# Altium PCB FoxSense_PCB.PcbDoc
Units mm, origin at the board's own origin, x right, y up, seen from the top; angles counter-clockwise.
Board outline 79.5 x 55 mm, 2 copper layers (Top Layer, Bottom Layer), stack 1.569 mm thick; 35 components, 44 nets, 152 pads, 33 vias.
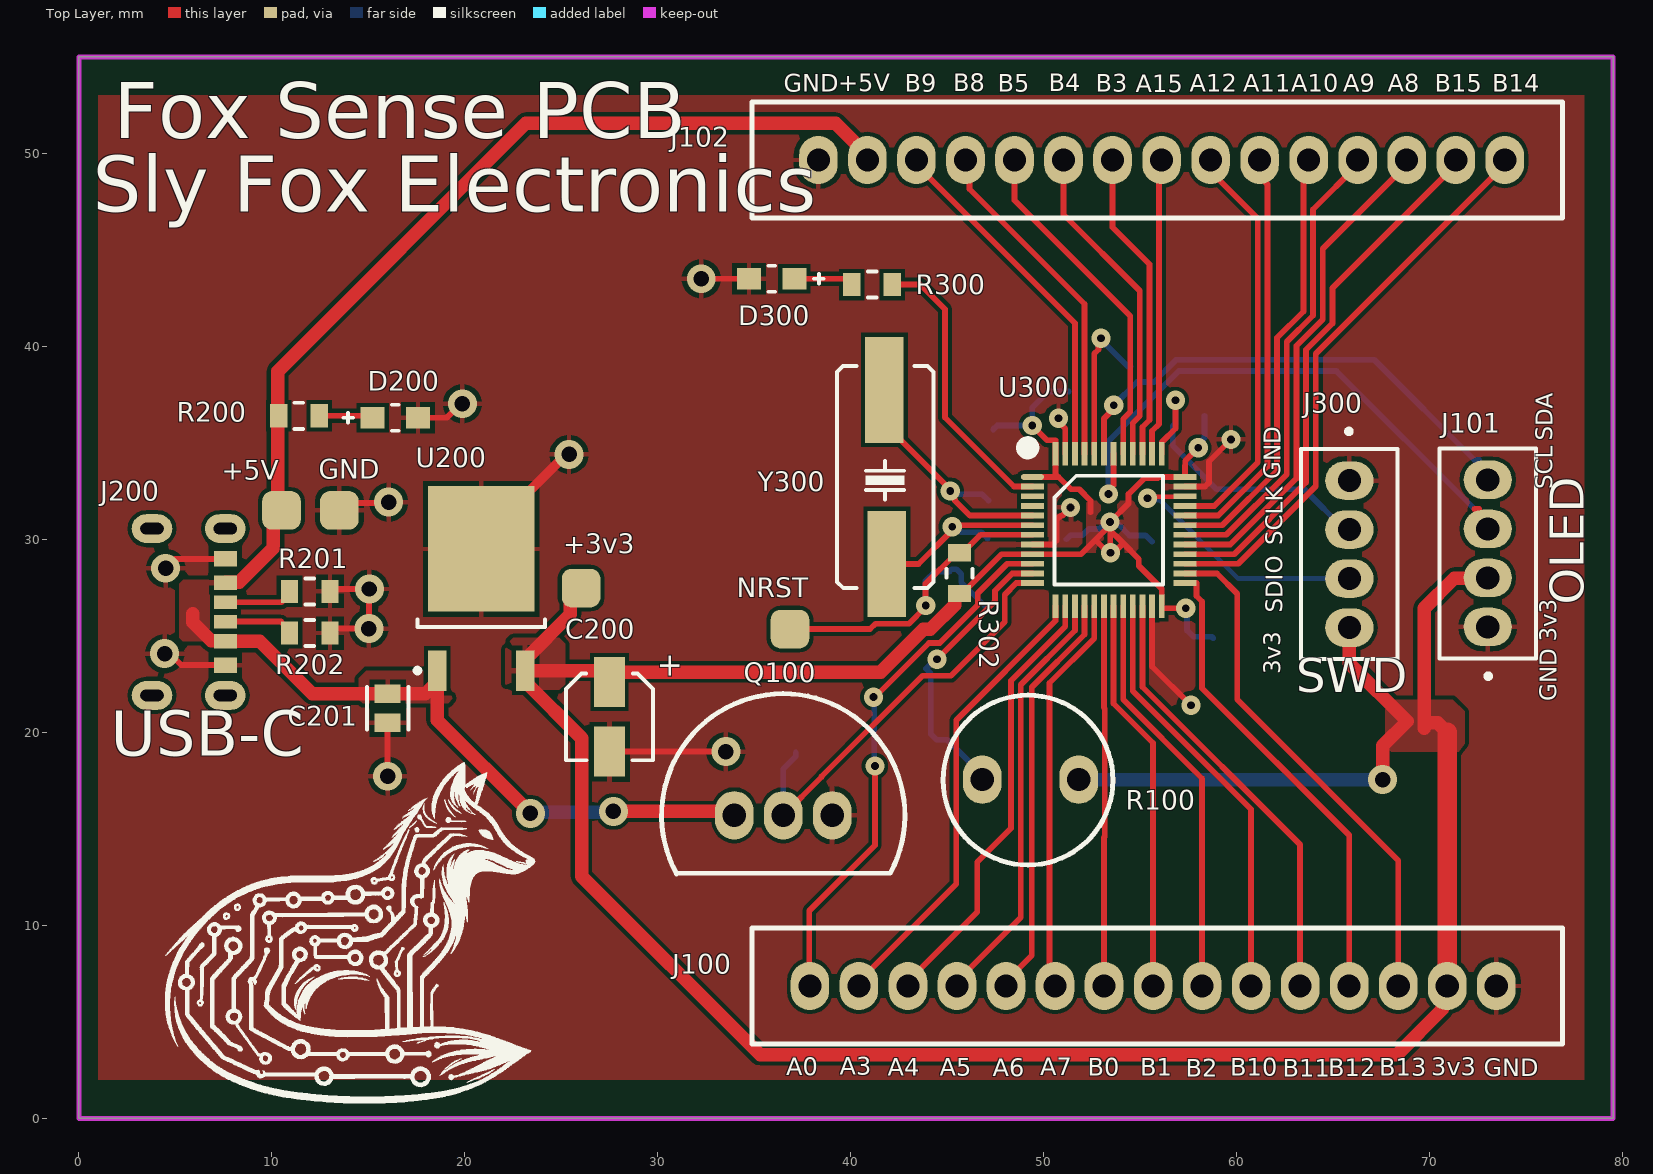
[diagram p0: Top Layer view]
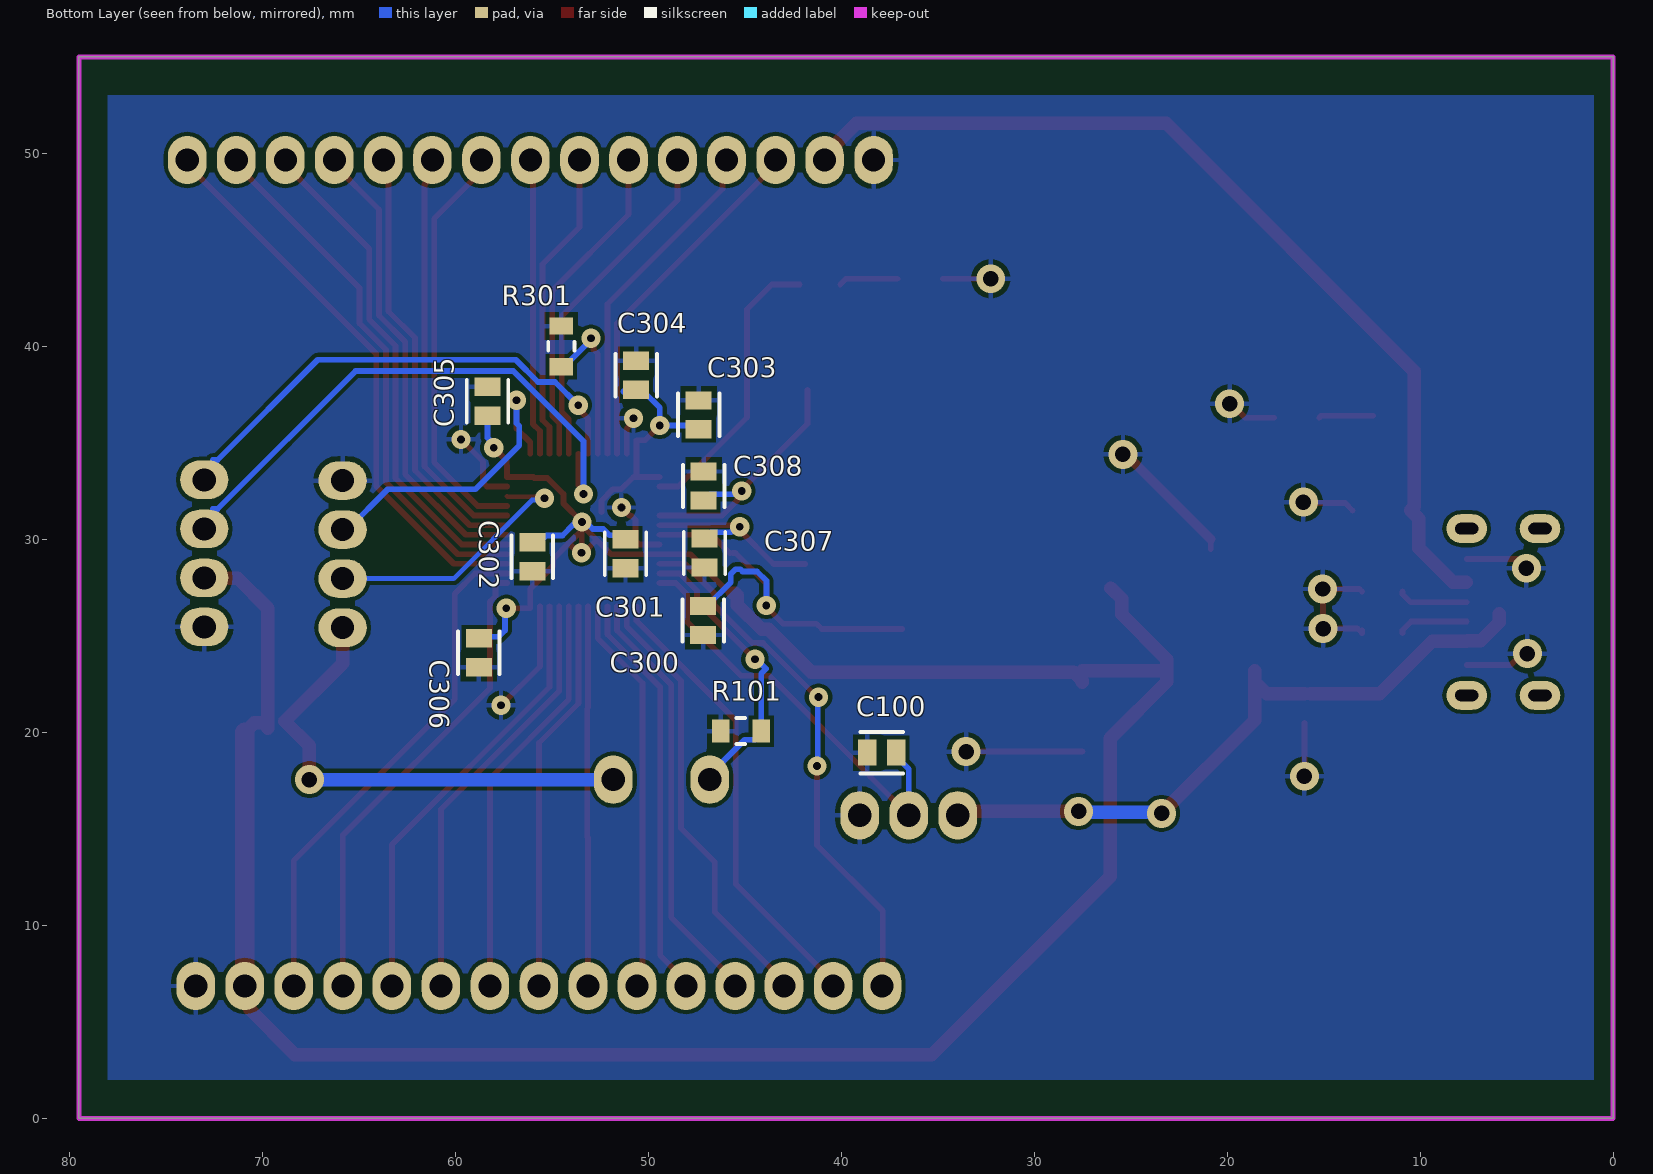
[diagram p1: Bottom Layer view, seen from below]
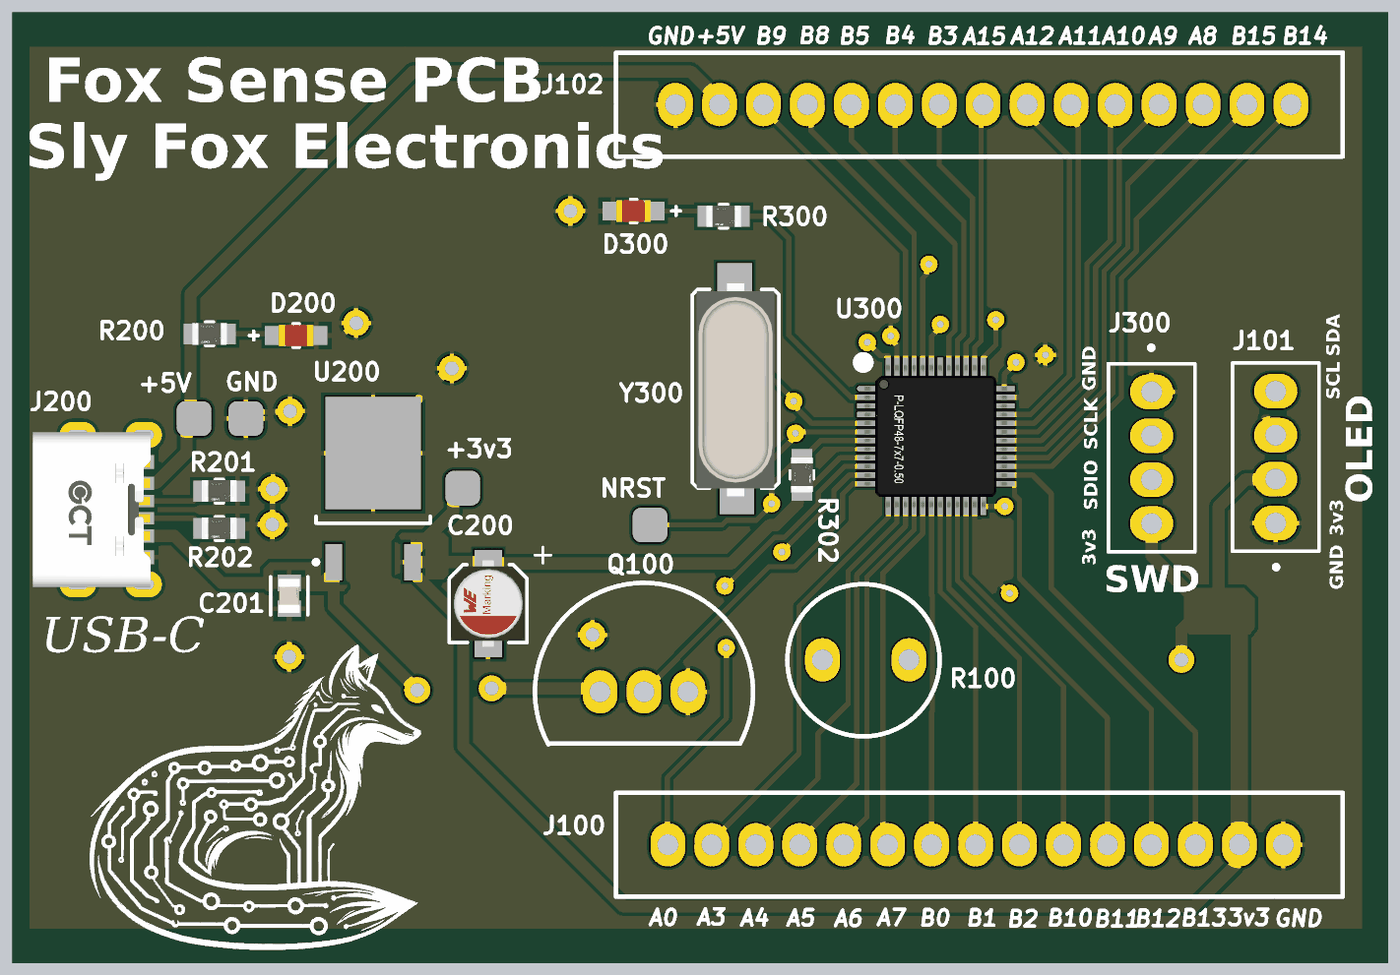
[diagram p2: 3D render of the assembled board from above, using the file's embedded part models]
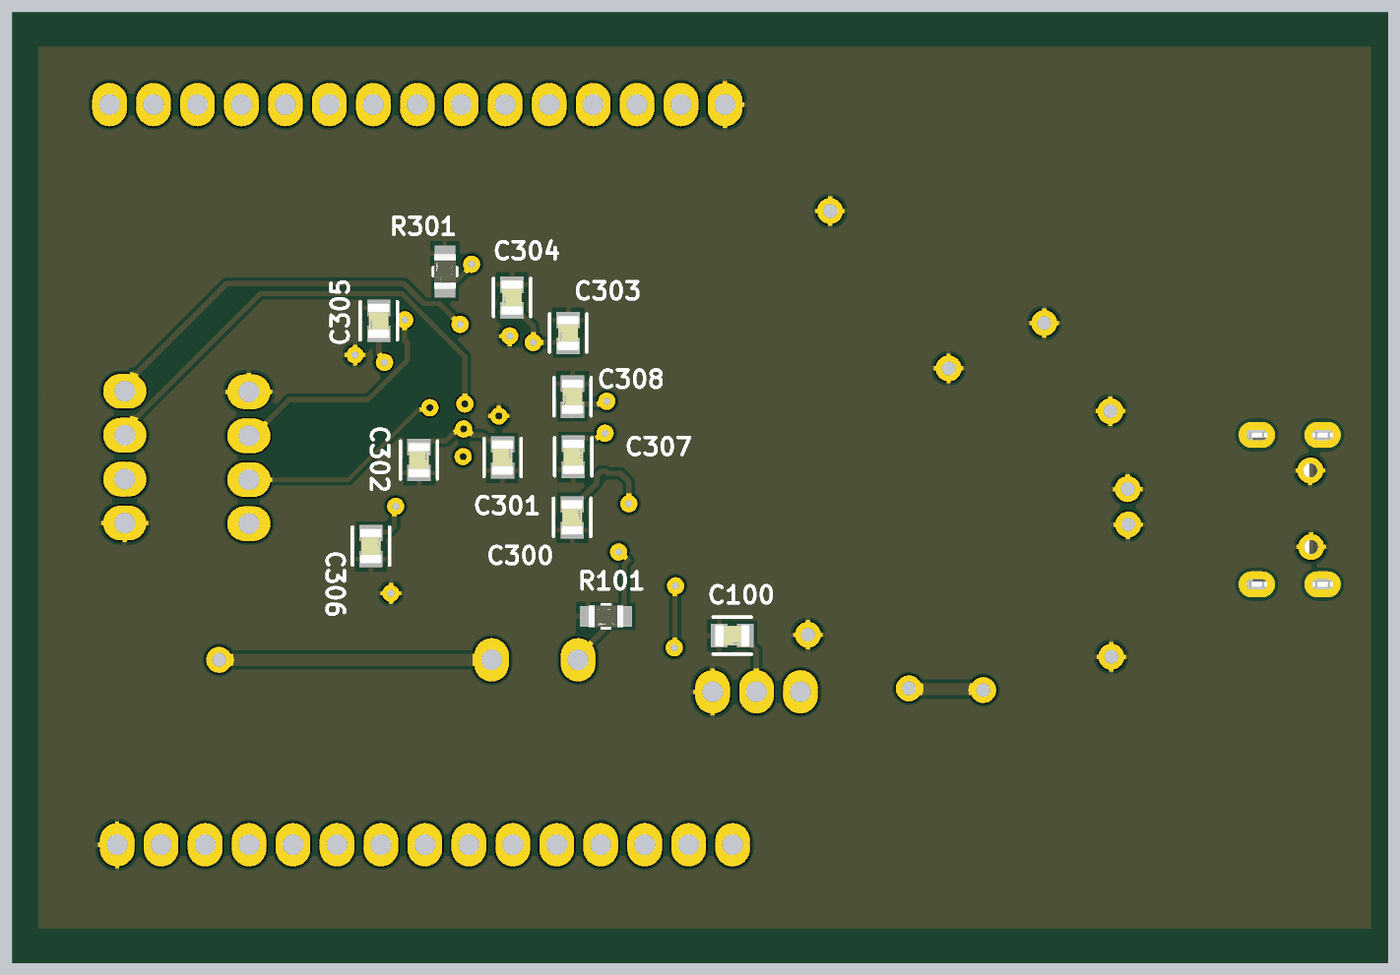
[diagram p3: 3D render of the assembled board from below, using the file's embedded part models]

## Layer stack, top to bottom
Top Solder: solder mask 0.0254, SM-001, Dk 4
Top Layer: signal copper 0.035
Dielectric 1: core 1.4986, Core-043, Dk 4.3
Bottom Layer: signal copper 0.035
Bottom Solder: solder mask 0.0254, SM-001, Dk 4

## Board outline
0,0 0,55 79.5,55 79.5,0

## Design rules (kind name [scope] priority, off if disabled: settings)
Clearance [All] p1: gap=0.2 ignorepadtopadclearanceinfootprint=TRUE
HoleSize [All] p1: absolutevalues=TRUE maxlimit=2.54 minlimit=0.04 maxpercent=80.000 minpercent=20.000
MinimumAnnularRing [All] p1: minimumring=0.3
MinimumSolderMaskSliver [All] p1: minsoldermaskwidth=0.2
PolygonConnect [All] p1: connectstyle=Relief reliefconductorwidth=0.254 reliefentries=4 polygonreliefangle="90 Angle" airgapwidth=0.254
RoutingVias [All] p1: holewidth=0.8 width=1.5 viastyle="Through Hole" minholewidth=0.4 minwidth=0.8 maxholewidth=0.8 maxwidth=1.5
SilkToSolderMaskClearance [IsPad] p1: minsilkscreentomaskgap=0.2 clearancetoexposedcopper=TRUE
SolderMaskExpansion [All] p1: expansion=0.102 istentingtop=FALSE
SupplyNets "Schematic Supply Nets" [InNet('GND')] p1: voltage=0.000
SupplyNets "Schematic Supply Nets_2" [InNet('+3v3')] p2: voltage=0.000
SupplyNets "Schematic Supply Nets_1" [InNet('+5V')] p3: voltage=0.000
Width [All] p1: maxlimit=2 minlimit=0.25 preferedwidth=0.7
27 further rules are at their usual default settings.

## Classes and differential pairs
component class FoxSense_Schematic: C100 J100 J101 J102 Q100 R100 R101
component class U_FoxSense_Power: +3v3 +5V C200 C201 D200 GND J200 R200 R201 R202 U200
component class U_FoxSense_Microcontroller: C300 C301 C302 C303 C304 C305 C306 C307 C308 D300 J300 NRST R300 R301 R302 U300 Y300

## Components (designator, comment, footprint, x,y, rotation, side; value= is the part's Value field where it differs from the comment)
+3v3 "Test_Point_SMD" TEST_Point_SMD 26,27.5 r90 top (schematic designator T201)
+5V "Test_Point_SMD" TEST_Point_SMD 10.475,31.525 r90 top (schematic designator T202)
C100 "100nF" Capacitor_SMD_0805 37.9,18.8 r270 bottom
C200 "2.2uF" Capacitor_SMD_Electrolyte_2.2uF 27.279,21.319 r90 top
C201 "100nF" Capacitor_SMD_0805 16.15,21.25 r0 top
C300 "100nF" Capacitor_SMD_0805 47.001,25.791 r180 bottom
C301 "100nF" Capacitor_SMD_0805 51.025,29.25 r180 bottom
C302 "1uF" Capacitor_SMD_0805 55.85,29.1 r180 bottom
C303 "10uF" Capacitor_SMD_0805 47.532,36.447 r0 bottom
C304 "100nF" Capacitor_SMD_0805 50.775,38.5 r0 bottom
C305 "100nF" Capacitor_SMD_0805 58.475,37.15 r0 bottom
C306 "100nF" Capacitor_SMD_0805 58.625,24.125 r180 bottom
C307 "20pF" Capacitor_SMD_0805 46.933,29.291 r180 bottom
C308 "20pF" Capacitor_SMD_0805 47.278,32.764 r0 bottom
D200 "LED_SMD_0805" LED_SMD_0805 16.1,36.2 r0 top
D300 "RED LED" LED_SMD_0805 36.2,43.6 r180 top
GND "Test_Point_SMD" TEST_Point_SMD 13.475,31.525 r90 top (schematic designator T200)
J100 "Header pin 15" Header15 37.88,6.881 r0 top
J101 "OLED" Header4 73,25.46 r90 top
J102 "Header pin 15" Header15 73.88,49.63 r180 top
J200 "USB_C_6_pin" USB_C_6_pin 4.792,26.16 r0 top
J300 "Pin_Header_4" Header4 65.831,33.045 r270 top
NRST "Test_Point_SMD" TEST_Point_SMD 36.825,25.375 r90 top (schematic designator T300)
Q100 "LM35 DZ" LM35 36.5,15.7 r180 top
R100 "LDR" LDR 49.183,17.524 r180 top
R101 "10K ohm" Resistor_SMD_0805 44.992,20.064 r0 bottom
R200 "330 ohm" Resistor_SMD_0805 11.6,36.4 r180 top
R201 "5.1k ohm" Resistor_SMD_0805 12.166,27.303 r180 top
R202 "5.1k ohm" Resistor_SMD_0805 12.166,25.144 r180 top
R300 "330 ohm" Resistor_SMD_0805 41.3,43.2 r180 top
R301 "10K ohm" Resistor_SMD_0805 54.5,39.8 r90 bottom
R302 "10K ohm" Resistor_SMD_0805 45.627,28.446 r270 top
U200 "LF33_DPAK" LF33 20.5,27.5 r0 top
U300 "STM32f103c8t6_LQFP48" STM32f103c8t6_LQFP48 49.411,33.232 r0 top
Y300 "XTAL 8MHz" Crystal_Resonator_SMD_XTAL 41.69,33.145 r0 top

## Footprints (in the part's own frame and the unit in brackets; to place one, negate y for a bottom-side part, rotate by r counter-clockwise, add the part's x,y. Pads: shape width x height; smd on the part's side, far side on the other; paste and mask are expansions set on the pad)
Capacitor_SMD_0805 [mm] "capacitor smd 0805"
  rect 1.35x0.95 smd paste+0 mask+0: 1(-0.15,0.75) 2(-0.15,-0.75)
  silkscreen extent -1.22,-1.1 0.92,1.1, body extent -0.77,-1 0.48,1, height 0.88
Capacitor_SMD_Electrolyte_2.2uF [mm] "Capacitor SMD Electrolyte 2.2uF"
  rect 2.6x1.6 smd: 1(1.281,-0.221) 2(-2.319,-0.221)
  silkscreen extent -2.77,-2.47 1.73,2.03, body extent -3.02,-2.37 1.98,1.93, height 5.5
Crystal_Resonator_SMD_XTAL [mm] "crystal ceramic resonator xtal"
  rect 2x5.5 smd: 1(0.176,-4.419) 2(0.049,4.598)
  silkscreen extent -2.4,-5.67 2.6,5.83, body extent -2.15,-6.13 2.35,6.17, height 5.18
Header4 [mm]
  oval 2x2.5 hole 1.2: 1(0,0) 2(2.54,0) 3(5.08,0) 4(7.62,0)
  silkscreen extent -2.67,-2.5 9.26,2.5
Header15 [mm] "Header pin 15"
  oval 2x2.5 hole 1.2: 1(0,-0.025) 2(2.54,-0.025) 3(5.08,-0.025) 4(7.62,-0.025) 5(10.16,-0.025) 6(12.7,-0.025) 7(15.24,-0.025) 8(17.78,-0.025) 9(20.32,-0.025) 10(22.86,-0.025) 11(25.4,-0.025) 12(27.94,-0.025) 13(30.48,-0.025) 14(33.02,-0.025) 15(35.56,-0.025)
  silkscreen extent -3,-3.03 39,2.97
LDR [mm] "LDR DIP"
  oval 2x2.5 hole 1.2: 1(-2.625,-0.025) 2(2.375,-0.025)
  silkscreen extent -4.4,-4.4 4.4,4.4
LED_SMD_0805 [mm] "LED SMD 0805"
  rect 1.25x1.1 smd paste+0 mask+0: 1(-0.875,0.1) 2(1.475,0.1)
  silkscreen extent -2.4,-0.58 0.48,0.77, body extent -1.6,-0.67 2.2,0.87, height 0.25
LF33 [mm] "LF33 DPAK 3.3 voltage regulator"
  rect 0.95x2.1 smd: 1(-1.93,-4.3) 3(2.63,-4.3)
  rect 5.5x6.5 smd: 4(0.35,2)
  silkscreen extent -3.08,-4.42 3.65,-1.65, body extent -2.95,-2.05 3.65,4.15, height 2.4
LM35 [mm] "LM35 DZ Dip"
  oval 2x2.5 hole 1.2: 1(2.54,0) 2(0,0) 3(-2.54,0)
  silkscreen extent -6.3,-6.3 6.3,3.04
Resistor_SMD_0805 [mm] "resistor smd 0805"
  rect 0.9x1.2 smd paste+0 mask+0: 1(-0.85,0) 2(1.25,0)
  silkscreen extent -0.03,-0.67 0.43,0.67, body extent -0.8,-0.63 1.2,0.63, height 0.6
STM32f103c8t6_LQFP48 [mm]
  oval 1.2x0.3 smd: 1(0,0)
  rect 1.2x0.3 smd: 2(0,-0.5) 3(0,-1) 4(0,-1.5) 5(0,-2) 6(0,-2.5) 7(0,-3) 8(0,-3.5) 9(0,-4) 10(0,-4.5) 11(0,-5) 12(0,-5.5) 25(7.9,-5.5) 26(7.9,-5) 27(7.9,-4.5) 28(7.9,-4) 29(7.9,-3.5) 30(7.9,-3) 31(7.9,-2.5) 32(7.9,-2) 33(7.9,-1.5) 34(7.9,-1) 35(7.9,-0.5) 36(7.9,0)
  rect 0.3x1.2 smd: 13(1.2,-6.7) 14(1.7,-6.7) 15(2.2,-6.7) 16(2.7,-6.7) 17(3.2,-6.7) 18(3.7,-6.7) 19(4.2,-6.7) 20(4.7,-6.7) 21(5.2,-6.7) 22(5.7,-6.7) 23(6.2,-6.7) 24(6.7,-6.7) 37(6.7,1.2) 38(6.2,1.2) 39(5.7,1.2) 40(5.2,1.2) 41(4.7,1.2) 42(4.2,1.2) 43(3.7,1.2) 44(3.2,1.2) 45(2.7,1.2) 46(2.2,1.2) 47(1.7,1.2) 48(1.2,1.2)
  silkscreen extent -0.54,-5.56 6.76,1.81, body extent -0.55,-7.25 8.45,1.75, height 1.4
TEST_Point_SMD [mm] "TEST_Point_SMD"
  rrect50% 2x2 smd: 1(-0.025,-0.025)
USB_C_6_pin [mm] "USB C connector 6 pin"
  rrect100% 2.1x1.5 hole 1.2 slot 0.6 at 90 deg paste-2539.97 mask+0: 2(2.8,-4.245) 3(-1,4.395) 3(2.8,4.395) 4(-1,-4.245)
  rect 1.2x0.7 smd paste+0 mask+0: A5(2.8,0.575) B5(2.8,-0.425)
  rect 1.2x0.76 smd paste+0 mask+0: A9(2.8,-1.445) B9(2.8,1.595)
  rect 1.2x0.8 smd paste+0 mask+0: A12(2.8,-2.675) B12(2.8,2.825)
  body extent -3.77,-4.89 3.75,5.05, height 0.25

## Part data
+3v3 +5V GND NRST: "Test Point SMD"
C100 C300 C301 C304 C305 C306: library part Capacitor_SMD_0805, "capacitor smd 0805 100nF"
C200: library part Capacitor_SMD_Electrolyte_2.2uF, "Capacitor SMD Electrolyte 2.2uF"
C201 C302: library part Capacitor_SMD_0805, "capacitor smd 0805"
C303: library part Capacitor_SMD_0805, "capacitor smd 0805 10uF"
C307 C308: library part Capacitor_SMD_0805, "capacitor smd 0805 20pF"
D200: "LED SMD 0805"
D300: library part LED_SMD_0805, "LED SMD 0805"
J100 J102: library part Header15
J101: library part Header4, "OLED 0..96 inch"
J200: library part USB_C, "USB C connector 6 pin"
J300: library part Header4, "Pin Header 4"
Q100: library part LM35
R100: "LDR DIP"
R101: library part Resistor_SMD_0805, "Resistor SMD 0805 10 k ohm"
R200 R201 R202: library part Resistor_SMD_0805, "Resistor SMD 0805"
R300: library part Resistor_SMD_0805, "Resistor SMD 0805 330 ohm"
R301 R302: library part Resistor_SMD_0805, "Resistor SMD 0805 10k ohm"
U200: library part LF33, "LF33 DPAK 3.3 voltage regulator"
U300: library part STM32f103c8t6, "STM32f103c8t6 LQFP48"
Y300: library part "Crystal Resonator SMD", "crystal resonator SMD 8MHz"

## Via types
v1: diameter 1, hole 0.4, Top Layer to Bottom Layer, 20 vias
v2: diameter 1.5, hole 0.8, Top Layer to Bottom Layer, 13 vias

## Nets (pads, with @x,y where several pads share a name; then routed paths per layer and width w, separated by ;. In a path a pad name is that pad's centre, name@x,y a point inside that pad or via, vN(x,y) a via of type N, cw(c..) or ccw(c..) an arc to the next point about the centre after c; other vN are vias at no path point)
+3v3: +3v3.1 C200.1 C301.1 C302.1 C303.1 C304.1 C305.1 C306.1 J100.14 J101.2 J300.4 R100.1 R302.2 U200.3 U300.1 U300.9 U300.24 U300.36 U300.48 | length 191.7
  Top Layer w0.3: R302.2 45.777,27.196 47.813,29.232 U300.9 51.932,29.232 52.616,29.916 ; v1(49.4,35.9) 50.167,35.133 50.611,35.133 U300.48 50.611,33.387 50.766,33.232 ; U300.1 50.766,33.232 ; 52.425,31.4 52.425,32.002 51.835,32.592 51.406,32.592 50.766,33.232 ; v1(57.35,26.425) 56.111,26.425 56.111,27.439 54.918,28.632 54.918,28.982 54.109,29.791 ; v1(57.996,34.746) 57.996,34.729 57.332,34.066 57.332,33.853 57.311,33.832 U300.36 55.956,33.232 55.906,33.182 55.23,33.182 54.394,32.347 54.394,31.869 v1(53.425,30.9) 53.437,30.888 53.437,29.312 v1(53.45,29.3) ; 52.616,29.916 52.723,29.916 53.339,29.3 v1(53.45,29.3) ; 52.616,29.916 53.3,30.6 54.109,29.791 ; v1(53.45,29.3) 53.618,29.3 54.109,29.791
  Top Layer w0.7: +3v3.1 25.468,26.918 25.468,26.113 23.13,23.775 U200.3 ; C200.1 27.5,22.675 27.95,23.125 41.556,23.125 43.765,25.334 44.119,25.334 45.377,26.592 45.377,27.096 45.477,27.196 R302.2 ; C200.1@27.5,23.2 U200.3 ; J300.4 65.831,23.569 68.825,20.575 67.55,19.3 v2(67.55,17.55) ; 69.7,20.2 69.7,26.418 71.266,27.984 73.05,27.984 J101.2@73.065,28 ; 70,20.5 70.4,20.5 70.9,20 ; J100.14@70.662,7.094 J100.14 70.651,6.607 70.651,5.651 68.3,3.3 35.3,3.3 26.05,12.55 26.05,19.705 23.13,22.625 U200.3
  Top Layer w1: J100.14 70.9,20
  Bottom Layer w0.3: C303.1 47.585,35.9 v1(49.4,35.9) 49.4,36.825 50.24,37.665 C304.1@51.292,37.665 ; C301.1 51.387,30.212 52,30.212 52.325,30.537 52.873,30.537 53.236,30.9 v1(53.425,30.9) 53.559,30.766 53.878,30.766 54.444,30.2 55.275,30.2 C302.1@55.6,29.875 ; v1(57.35,26.425) 57.425,26.35 57.425,25.275 57.75,24.95 58.7,24.95 C306.1 ; v1(57.996,34.746) 57.996,34.935 58.325,35.264 C305.1
  Bottom Layer w0.7: R100.1 v2(67.55,17.55)
+5V: +5V.1 C201.1 J102.14 J200.A9 J200.B9 Q100.1 R200.2 U200.1 | length 84.3
  Top Layer w0.3: J200.B9 7.622,27.785 J200.B9@7.737,27.9
  Top Layer w0.7: 5.9,26.15 5.9,25.699 6.854,24.745 7.562,24.745 J200.A9 9.376,24.715 12.091,22 C201.1@15.675,22 ; J200.B9@7.622,27.785 8.311,27.785 10.075,29.549 10.075,31.075 +5V.1 10.3,31.7 10.3,36.4 10.3,38.7 23.155,51.555 39.21,51.555 40.86,49.905 J102.14 ; C201.1 17.945,22 U200.1@18.57,22.625 ; U200.1 U200.1@18.57,22.625 ; v2(23.4,15.8) 18.57,20.63 U200.1@18.57,22.625 ; v2(27.7,15.9) 33.76,15.9 Q100.1
  Bottom Layer w0.7: v2(23.4,15.8) 23.45,15.85 27.65,15.85 v2(27.7,15.9)
ADC1: R100.2 R101.1 U300.11 | length 15.2
  Top Layer w0.3: v1(44.467,23.784) 47.473,26.789 47.473,27.339 48.366,28.232 U300.11
  Bottom Layer w0.3: v1(44.467,23.784) 44.384,23.784 43.896,23.296 44.142,23.05 44.142,19.914 44.442,19.614 44.993,19.614 46.808,17.799 R100.2
ADC2: C100.1 Q100.2 U300.12 | length 22.3
  Top Layer w0.3: Q100.2 38.484,17.684 38.484,17.709 43.709,22.934 45.184,22.934 47.973,25.723 47.973,27.131 48.573,27.732 U300.12
  Bottom Layer w0.3: Q100.2 36.5,18.1 37.15,18.75 C100.1
BOOT0: R301.1 U300.44 | length 8.3
  Top Layer w0.3: U300.44 52.611,39.626 52.827,39.842 52.827,40.291 v1(52.961,40.425)
  Bottom Layer w0.3: v1(52.961,40.425) 52.961,40.339 54.35,38.95 R301.1
CC1: J200.A5 R201.2 | length 3.6
  Top Layer w0.3: J200.A5 10.498,26.735 10.916,27.153 R201.2
CC2: J200.B5 R202.2 | length 3.7
  Top Layer w0.3: J200.B5 10.475,25.735 10.916,25.294 R202.2
GND: C100.2 C200.2 C201.2 C300.2 C301.2 C302.2 C303.2 C304.2 C305.2 C306.2 C307.2 C308.2 D200.2 D300.2 GND.1 J100.15 J101.1 J102.15 J200.A12 J200.B12 J300.1 Q100.3 R101.2 R201.1 R202.1 R301.2 U200.4 U300.8 U300.23 U300.35 U300.47 | length 51.9
  Top Layer w0.3: v2(4.45,24.075) 4.712,24.075 5.302,23.485 J200.A12 ; v2(4.5,28.5) 4.985,28.985 J200.B12 ; R202.1@13.016,25.294 R202.1 13.247,25.375 v2(15.025,25.375) 15.038,25.388 15.038,27.413 v2(15.05,27.425) 13.138,27.425 R201.1 ; GND.1 13.887,31.888 16.012,31.888 v2(16.05,31.925) ; v2(16,17.725) C201.2 ; D200.2 19.066,36.3 19.791,37.025 v2(19.875,37.025) ; U200.4 U200.4@20.85,30 ; C200.2 v2(33.525,19) ; v2(32.25,43.5) D300.2 ; U300.8 50.456,29.732 50.661,29.937 50.661,31.008 50.873,31.22 50.956,31.22 v1(51.386,31.65) ; v1(50.761,36.275) 50.761,36.086 51.111,35.736 U300.47 ; U300.23 55.611,23.414 v1(57.625,21.4) ; U300.35 58.356,32.732 58.561,32.937 58.561,34.036 v1(59.7,35.175)
  Top Layer w0.5: U200.4@20.85,30 25.25,34.4 v2(25.4,34.4)
MCU_LED_Anode: D300.1 R300.2 | length 3.1
  Top Layer w0.3: D300.1 39.75,43.5 R300.2
NRST: C300.1 NRST.1 R302.1 U300.7 | length 21
  Top Layer w0.3: NRST.1 40.999,25.35 41.275,25.626 43.011,25.626 43.875,26.49 43.875,27.694 45.477,29.296 R302.1 ; R302.1@45.777,29.296 46.713,30.232 U300.7
  Bottom Layer w0.3: v1(43.875,26.575) 43.875,27.85 44.359,28.334 45.114,28.334 45.23,28.45 45.479,28.45 45.723,28.206 45.723,27.769 46.951,26.541 C300.1
OSC_IN: C308.1 U300.5 Y300.2 | length 13.8
  Top Layer w0.3: Y300.2 41.739,35.993 45.15,32.582 45.15,32.311 45.397,32.064 45.397,32.003 46.168,31.232 U300.5
  Bottom Layer w0.3: v1(45.15,32.5) 45.339,32.5 45.5,32.339 46.803,32.339 C308.1
OSC_OUT: C307.1 U300.6 Y300.1 | length 10.6
  Top Layer w0.3: Y300.1 43.501,28.726 45.25,30.475 v1(45.25,30.65) 45.332,30.732 U300.6
  Bottom Layer w0.3: v1(45.25,30.65) 45.439,30.65 45.724,30.366 46.758,30.366 C307.1
PA0: J100.1 U300.10 | length 27.9
  Top Layer w0.3: J100.1 37.85,6.886 37.85,10.75 41.25,14.15 v1(41.25,18.25) ; v1(41.175,21.825) 41.246,21.825 44.055,24.634 44.61,24.634 46.577,26.601 46.577,27.202 48.107,28.732 U300.10
  Bottom Layer w0.3: v1(41.175,21.825) 41.212,21.788 41.212,18.288 v1(41.25,18.25)
PA3: J100.2 U300.13 | length 23.9
  Top Layer w0.3: J100.2 40.42,7.106 45.458,12.144 45.458,20.629 50.611,25.782 U300.13
PA4: J100.3 U300.14 | length 23.1
  Top Layer w0.3: J100.3 42.96,7.106 46.55,10.696 46.55,13.275 48.3,15.025 48.3,22.676 51.111,25.487 U300.14
PA5: J100.4 U300.15 | length 22.2
  Top Layer w0.3: J100.4 45.5,7.106 48.8,10.406 48.8,22.469 51.611,25.28 U300.15
PA6: J100.5 U300.16 | length 21.4
  Top Layer w0.3: J100.5 48.04,7.106 49.375,8.441 49.375,22.337 52.111,25.073 U300.16
PA7: J100.6 U300.17 | length 20.7
  Top Layer w0.3: J100.6 50.3,7.136 50.3,22.555 52.611,24.866 U300.17
PA8: J102.3 U300.29 | length 26.1
  Top Layer w0.3: U300.29 59.66,29.732 63.087,33.158 63.087,40.026 64.45,41.389 64.45,45.055 68.8,49.405 J102.3
PA9: J102.4 U300.30 | length 24.4
  Top Layer w0.3: U300.30 59.453,30.232 62.587,33.365 62.587,40.233 63.95,41.596 63.95,47.095 66.26,49.405 J102.4
PA10: J102.5 U300.31 | length 22.7
  Top Layer w0.3: U300.31 59.246,30.732 62.087,33.573 62.087,40.442 63.45,41.805 63.45,49.385 J102.5
PA11: J102.6 U300.32 | length 21.4
  Top Layer w0.3: U300.32 59.039,31.232 61.587,33.78 61.587,48.379 61.505,48.461 61.505,49.33 J102.6
PA12: J102.7 U300.33 | length 21.4
  Top Layer w0.3: U300.33 58.832,31.732 61.087,33.987 61.087,46.628 58.64,49.074 J102.7
PA15: J102.8 U300.38 | length 15.4
  Top Layer w0.3: U300.38 55.611,35.613 55.975,35.977 55.975,49.53 J102.8
PB0: J100.7 U300.18 | length 19.7
  Top Layer w0.3: U300.18 53.111,21.284 53.158,21.237 53.158,14.583 53.12,14.545 J100.7
PB1: J100.8 U300.19 | length 20.5
  Top Layer w0.3: U300.19 53.611,21.492 55.66,19.443 J100.8
PB2: J100.9 U300.20 | length 21.4
  Top Layer w0.3: U300.20 54.111,21.699 58.2,17.61 J100.9
PB3: J102.9 U300.39 | length 16.2
  Top Layer w0.3: J102.9 53.56,46.165 55.475,44.25 55.475,36.184 55.111,35.82 U300.39
PB4: J102.10 U300.40 | length 17
  Top Layer w0.3: J102.10 51.02,46.83 54.975,42.875 54.975,36.391 54.611,36.027 U300.40
PB5: J102.11 U300.41 | length 17.9
  Top Layer w0.3: J102.11 48.48,47.572 54.475,41.577 54.475,36.598 54.111,36.234 U300.41
PB8: J102.12 U300.45 | length 17.8
  Top Layer w0.3: J102.12 46.143,49.452 46.143,48.157 52.111,42.189 U300.45
PB9: J102.13 U300.46 | length 18.6
  Top Layer w0.3: J102.13 43.4,49.405 51.611,41.194 U300.46
PB10: J100.10 U300.21 | length 22.2
  Top Layer w0.3: U300.21 54.611,22.139 60.74,16.01 J100.10
PB11: J100.11 U300.22 | length 23.1
  Top Layer w0.3: U300.22 55.111,22.346 63.28,14.177 J100.11
PB12: J100.12 U300.25 | length 24.8
  Top Layer w0.3: U300.25 57.911,27.732 57.911,27.066 58.2,26.777 58.2,22.286 65.82,14.666 J100.12
PB13: J100.13 U300.26 | length 26.9
  Top Layer w0.3: U300.26 58.968,28.232 60.025,27.175 60.025,21.7 68.36,13.365 J100.13
PB14: J102.1 U300.27 | length 29.4
  Top Layer w0.3: U300.27 60.075,28.732 64.087,32.744 64.087,39.612 73.88,49.405 J102.1
PB15: J102.2 U300.28 | length 27.7
  Top Layer w0.3: U300.28 59.868,29.232 63.587,32.951 63.587,39.819 64.95,41.182 64.95,43.015 71.34,49.405 J102.2
PC13: R300.1 U300.2 | length 14.9
  Top Layer w0.3: R300.1 43.599,43.2 44.875,41.924 44.875,36.311 48.454,32.732 U300.2
Power_LED_Anode: D200.1 R200.1 | length 2.8
  Top Layer w0.3: R200.1 15.125,36.4 D200.1
SCL: J101.3 U300.42 | length 28.9
  Top Layer w0.3: v1(53.35,32.35) 53.35,32.539 53.611,32.8 U300.42 ; 72.312,31.57 72.562,31.57
  Bottom Layer w0.3: v1(53.35,32.35) 53.35,35.085 56.99,38.725 65.157,38.725 72.312,31.57 72.562,31.57
SDA: J101.4 U300.43 | length 24.8
  Top Layer w0.3: U300.43 53.111,36.247 53.625,36.761 v1(53.625,36.95)
  Bottom Layer w0.3: v1(53.625,36.95) 54.825,38.15 55.708,38.15 56.858,39.3 67.122,39.3 72.312,34.11 72.562,34.11
SWCLK: J300.2 U300.37 | length 16.7
  Top Layer w0.3: U300.37 56.111,35.032 56.825,35.746 v1(56.825,37.208) ; J300.2@65.581,30.505 J300.2
  Bottom Layer w0.3: v1(56.825,37.208) 56.825,36.017 56.675,35.867 56.675,34.864 58.942,32.597 63.489,32.597 65.581,30.505 J300.2
SWDIO: J300.3 U300.34 | length 14.2
  Top Layer w0.25: v1(55.375,32.125) 55.457,32.207 57.286,32.207 U300.34
  Bottom Layer w0.25: v1(55.375,32.125) 55.469,32.031 56.019,32.031 60.085,27.965 J300.3
pads on no net: J200.2 J200.3 J200.4 U300.3 U300.4

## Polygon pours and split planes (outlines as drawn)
GND on Top Layer "NONET_L-01_P-001" (solid, remove dead copper, pour order 7): 1,2 1,53 78,53 78,2
+3v3 on Top Layer "NONET_L-01_P-001" (solid, remove dead copper, pour order 2): 22.1,24.5 22.5,24.9 24.9,24.9 25.2,24.6 25.2,22.5 24.9,22.2 22.2,22.2 22.1,22.3
+5V on Top Layer "NONET_L-01_P-001" (solid, remove dead copper, pour order 1): 14.5,22.8 14.9,23.2 19.3,23.2 19.5,23 19.5,21.7 19.3,21.5 14.7,21.5 14.5,21.7
+5V on Top Layer "NONET_L-01_P-001" (solid, remove dead copper, pour order 0): 7.592,27.755 7.447,27.9 5.4,27.9 5.2,27.7 5.2,24.9 5.385,24.715 7.592,24.715
+3v3 on Top Layer "NONET_L-01_P-001" (solid, remove dead copper, pour order 4): 52.2,31.9 52.3,32 54.6,32 54.9,31.7 54.9,29.5 54.7,29.3 52.2,29.3
+3v3 on Top Layer "NONET_L-01_P-001" (solid, remove dead copper, pour order 3): 71.8,19.4 71.8,21.1 71.2,21.7 68.2,21.7 67.7,21.2 67.7,19.3 68,19 71.5,19
GND on Bottom Layer "NONET_L-01_P-001" (solid, remove dead copper, pour order 6): 78,53 78,2 1,2 1,53

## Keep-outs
Keep-Out Layer:
  the board outline again, w0.254

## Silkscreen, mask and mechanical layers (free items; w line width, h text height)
Top Overlay:
  drawing of 34 lines, arcs and shapes, not listed
  text "+5V" at 39.35,53.225 h0.9
  text "B8" at 45.3,53.225 h0.9
  text "B4" at 50.25,53.225 h0.9
  text "GND" at 36.525,53.2 h0.9
  text "B9" at 42.8,53.2 h0.9
  text "B5" at 47.625,53.2 h0.9
  text "B3" at 52.7,53.2 h0.9
  text "A12" at 57.55,53.2 h0.9
  text "A11" at 60.325,53.2 h0.9
  text "A10" at 62.825,53.2 h0.9
  text "A9" at 65.525,53.2 h0.9
  text "A8" at 67.825,53.2 h0.9
  text "B15" at 70.25,53.2 h0.9
  text "B14" at 73.225,53.2 h0.9
  text "A15" at 54.775,53.175 h0.9
  text "Fox Sense PCB" at 1.801,49.821 h5
  text "Sly Fox Electronics" at 0.731,46.002 h5
  text "SDA" at 76.686,35.1 h1.5 r90
  text "GND" at 62.586,33.1 h1.5 r90
  text "SCL" at 76.686,32.6 h1.5 r90
  text "SCLK" at 62.686,29.7 h1.5 r90
  text "OLED" at 78.572,26.6 h3 r90
  text "SDIO" at 62.686,26.2 h1.5 r90
  text "3v3" at 76.886,24.7 h1.5 r90
  text "3v3" at 62.586,23 h1.5 r90
  text "GND" at 76.886,21.6 h1.5 r90
  text "SWD" at 63.075,21.478 h3
  text "USB-C" at 1.656,18.005 h4
  text "A3" at 39.425,2.25 h0.9
  text "A0" at 36.65,2.225 h0.9
  text "A7" at 49.825,2.225 h0.9
  text "3v3" at 70.075,2.225 h0.9
  text "A4" at 41.925,2.2 h0.9
  text "A5" at 44.6,2.2 h0.9
  text "B0" at 52.275,2.2 h0.9
  text "B1" at 55,2.2 h0.9
  text "B10" at 59.65,2.2 h0.9
  text "B13" at 67.375,2.2 h0.9
  text "A6" at 47.35,2.175 h0.9
  text "B12" at 64.725,2.175 h0.9
  text "GND" at 72.8,2.175 h0.9
  text "B2" at 57.35,2.15 h0.9
  text "B11" at 62.375,2.15 h0.9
